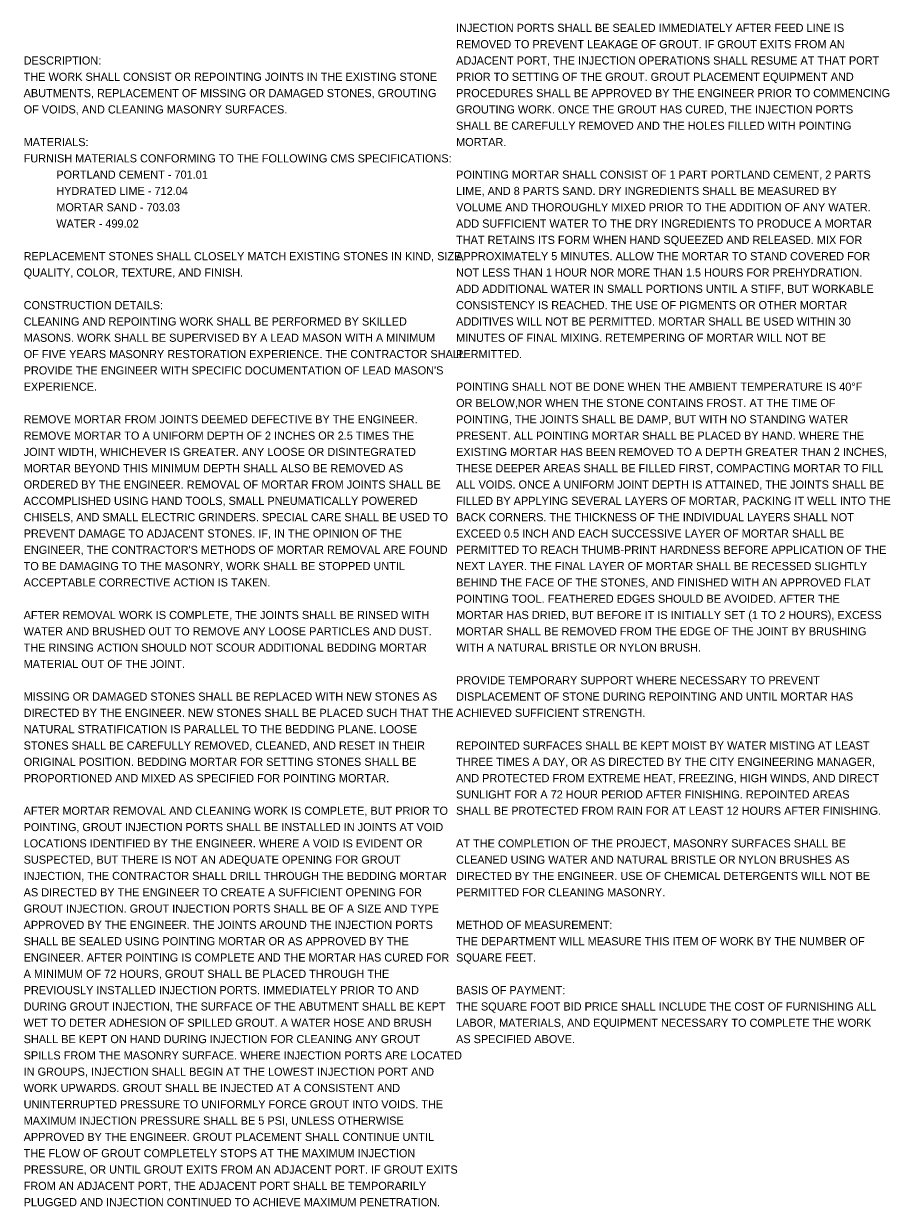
# Model space of a CAD drawing. Extents: x 0 to 59.1, y 0 to 43.6.
# Drawn here: x 9.82 to 24.69, y 23.33 to 43.63 of the extents above; entities that cross this region are included whole.
import ezdxf

# ---------------------------------------------------------------- set-up
doc = ezdxf.new("R2010")
doc.units = 0
doc.layers.add('SH_Text', color=7, linetype='Continuous')

msp = doc.modelspace()

# ---------------------------------------------------------------- texts
at = {"layer": 'SH_Text'}
for s, p in [('INJECTION PORTS SHALL BE SEALED IMMEDIATELY AFTER FEED LINE IS ', (17.24, 43.491)), ('REMOVED TO PREVENT LEAKAGE OF GROUT. IF GROUT EXITS FROM AN ', (17.24, 43.211)), ('DESCRIPTION:', (9.82, 42.931)), ('ADJACENT PORT, THE INJECTION OPERATIONS SHALL RESUME AT THAT PORT ', (17.24, 42.931)), ('THE WORK SHALL CONSIST OR REPOINTING JOINTS IN THE EXISTING STONE ', (9.82, 42.651)), ('PRIOR TO SETTING OF THE GROUT. GROUT PLACEMENT EQUIPMENT AND ', (17.24, 42.651)), ('ABUTMENTS, REPLACEMENT OF MISSING OR DAMAGED STONES, GROUTING ', (9.82, 42.371)), ('PROCEDURES SHALL BE APPROVED BY THE ENGINEER PRIOR TO COMMENCING ', (17.24, 42.371)), ('OF VOIDS, AND CLEANING MASONRY SURFACES.', (9.82, 42.091)), ('GROUTING WORK. ONCE THE GROUT HAS CURED, THE INJECTION PORTS ', (17.24, 42.091)), ('SHALL BE CAREFULLY REMOVED AND THE HOLES FILLED WITH POINTING ', (17.24, 41.811)), ('MATERIALS:', (9.82, 41.531)), ('MORTAR.', (17.24, 41.531)), ('FURNISH MATERIALS CONFORMING TO THE FOLLOWING CMS SPECIFICATIONS:', (9.82, 41.251)), ('PORTLAND CEMENT - 701.01', (10.38, 40.971)), ('POINTING MORTAR SHALL CONSIST OF 1 PART PORTLAND CEMENT, 2 PARTS ', (17.24, 40.971)), ('HYDRATED LIME - 712.04', (10.38, 40.691)), ('LIME, AND 8 PARTS SAND. DRY INGREDIENTS SHALL BE MEASURED BY ', (17.24, 40.691)), ('MORTAR SAND - 703.03', (10.38, 40.411)), ('VOLUME AND THOROUGHLY MIXED PRIOR TO THE ADDITION OF ANY WATER. ', (17.24, 40.411)), ('WATER - 499.02', (10.38, 40.131)), ('ADD SUFFICIENT WATER TO THE DRY INGREDIENTS TO PRODUCE A MORTAR ', (17.24, 40.131)), ('THAT RETAINS ITS FORM WHEN HAND SQUEEZED AND RELEASED. MIX FOR ', (17.24, 39.851)), ('REPLACEMENT STONES SHALL CLOSELY MATCH EXISTING STONES IN KIND, SIZE, ', (9.82, 39.571)), ('APPROXIMATELY 5 MINUTES. ALLOW THE MORTAR TO STAND COVERED FOR ', (17.24, 39.571)), ('QUALITY, COLOR, TEXTURE, AND FINISH.', (9.82, 39.291)), ('NOT LESS THAN 1 HOUR NOR MORE THAN 1.5 HOURS FOR PREHYDRATION. ', (17.24, 39.291)), ('ADD ADDITIONAL WATER IN SMALL PORTIONS UNTIL A STIFF, BUT WORKABLE ', (17.24, 39.011)), ('CONSTRUCTION DETAILS:', (9.82, 38.731)), ('CONSISTENCY IS REACHED. THE USE OF PIGMENTS OR OTHER MORTAR ', (17.24, 38.731)), ('CLEANING AND REPOINTING WORK SHALL BE PERFORMED BY SKILLED ', (9.82, 38.451)), ('ADDITIVES WILL NOT BE PERMITTED. MORTAR SHALL BE USED WITHIN 30 ', (17.24, 38.451)), ('MASONS. WORK SHALL BE SUPERVISED BY A LEAD MASON WITH A MINIMUM ', (9.82, 38.171)), ('MINUTES OF FINAL MIXING. RETEMPERING OF MORTAR WILL NOT BE ', (17.24, 38.171)), ('OF FIVE YEARS MASONRY RESTORATION EXPERIENCE. THE CONTRACTOR SHALL ', (9.82, 37.891)), ('PERMITTED.', (17.24, 37.891)), ("PROVIDE THE ENGINEER WITH SPECIFIC DOCUMENTATION OF LEAD MASON'S", (9.82, 37.611)), ('EXPERIENCE.', (9.82, 37.331)), ('POINTING SHALL NOT BE DONE WHEN THE AMBIENT TEMPERATURE IS 40°F ', (17.24, 37.331)), ('OR BELOW,NOR WHEN THE STONE CONTAINS FROST. AT THE TIME OF ', (17.24, 37.051)), ('REMOVE MORTAR FROM JOINTS DEEMED DEFECTIVE BY THE ENGINEER. ', (9.82, 36.771)), ('POINTING, THE JOINTS SHALL BE DAMP, BUT WITH NO STANDING WATER ', (17.24, 36.771)), ('REMOVE MORTAR TO A UNIFORM DEPTH OF 2 INCHES OR 2.5 TIMES THE ', (9.82, 36.491)), ('PRESENT. ALL POINTING MORTAR SHALL BE PLACED BY HAND. WHERE THE ', (17.24, 36.491)), ('JOINT WIDTH, WHICHEVER IS GREATER. ANY LOOSE OR DISINTEGRATED ', (9.82, 36.211)), ('EXISTING MORTAR HAS BEEN REMOVED TO A DEPTH GREATER THAN 2 INCHES, ', (17.24, 36.211)), ('MORTAR BEYOND THIS MINIMUM DEPTH SHALL ALSO BE REMOVED AS ', (9.82, 35.931)), ('THESE DEEPER AREAS SHALL BE FILLED FIRST, COMPACTING MORTAR TO FILL ', (17.24, 35.931)), ('ORDERED BY THE ENGINEER. REMOVAL OF MORTAR FROM JOINTS SHALL BE ', (9.82, 35.651)), ('ALL VOIDS. ONCE A UNIFORM JOINT DEPTH IS ATTAINED, THE JOINTS SHALL BE ', (17.24, 35.651)), ('ACCOMPLISHED USING HAND TOOLS, SMALL PNEUMATICALLY POWERED ', (9.82, 35.371)), ('FILLED BY APPLYING SEVERAL LAYERS OF MORTAR, PACKING IT WELL INTO THE ', (17.24, 35.371)), ('CHISELS, AND SMALL ELECTRIC GRINDERS. SPECIAL CARE SHALL BE USED TO ', (9.82, 35.091)), ('BACK CORNERS. THE THICKNESS OF THE INDIVIDUAL LAYERS SHALL NOT ', (17.24, 35.091)), ('PREVENT DAMAGE TO ADJACENT STONES. IF, IN THE OPINION OF THE ', (9.82, 34.811)), ('EXCEED 0.5 INCH AND EACH SUCCESSIVE LAYER OF MORTAR SHALL BE ', (17.24, 34.811)), ("ENGINEER, THE CONTRACTOR'S METHODS OF MORTAR REMOVAL ARE FOUND ", (9.82, 34.531)), ('PERMITTED TO REACH THUMB-PRINT HARDNESS BEFORE APPLICATION OF THE ', (17.24, 34.531)), ('TO BE DAMAGING TO THE MASONRY, WORK SHALL BE STOPPED UNTIL ', (9.82, 34.251)), ('NEXT LAYER. THE FINAL LAYER OF MORTAR SHALL BE RECESSED SLIGHTLY ', (17.24, 34.251)), ('ACCEPTABLE CORRECTIVE ACTION IS TAKEN.', (9.82, 33.971)), ('BEHIND THE FACE OF THE STONES, AND FINISHED WITH AN APPROVED FLAT ', (17.24, 33.971)), ('POINTING TOOL. FEATHERED EDGES SHOULD BE AVOIDED. AFTER THE ', (17.24, 33.691)), ('AFTER REMOVAL WORK IS COMPLETE, THE JOINTS SHALL BE RINSED WITH ', (9.82, 33.411)), ('MORTAR HAS DRIED, BUT BEFORE IT IS INITIALLY SET (1 TO 2 HOURS), EXCESS ', (17.24, 33.411)), ('WATER AND BRUSHED OUT TO REMOVE ANY LOOSE PARTICLES AND DUST. ', (9.82, 33.131)), ('MORTAR SHALL BE REMOVED FROM THE EDGE OF THE JOINT BY BRUSHING ', (17.24, 33.131)), ('THE RINSING ACTION SHOULD NOT SCOUR ADDITIONAL BEDDING MORTAR ', (9.82, 32.851)), ('WITH A NATURAL BRISTLE OR NYLON BRUSH.', (17.24, 32.851)), ('MATERIAL OUT OF THE JOINT.', (9.82, 32.571)), ('PROVIDE TEMPORARY SUPPORT WHERE NECESSARY TO PREVENT ', (17.24, 32.291)), ('MISSING OR DAMAGED STONES SHALL BE REPLACED WITH NEW STONES AS ', (9.82, 32.011)), ('DISPLACEMENT OF STONE DURING REPOINTING AND UNTIL MORTAR HAS ', (17.24, 32.011)), ('DIRECTED BY THE ENGINEER. NEW STONES SHALL BE PLACED SUCH THAT THE ', (9.82, 31.731)), ('ACHIEVED SUFFICIENT STRENGTH.', (17.24, 31.731)), ('NATURAL STRATIFICATION IS PARALLEL TO THE BEDDING PLANE. LOOSE ', (9.82, 31.451)), ('STONES SHALL BE CAREFULLY REMOVED, CLEANED, AND RESET IN THEIR ', (9.82, 31.171)), ('REPOINTED SURFACES SHALL BE KEPT MOIST BY WATER MISTING AT LEAST ', (17.24, 31.171)), ('ORIGINAL POSITION. BEDDING MORTAR FOR SETTING STONES SHALL BE ', (9.82, 30.891)), ('THREE TIMES A DAY, OR AS DIRECTED BY THE CITY ENGINEERING MANAGER, ', (17.24, 30.891)), ('PROPORTIONED AND MIXED AS SPECIFIED FOR POINTING MORTAR.', (9.82, 30.611)), ('AND PROTECTED FROM EXTREME HEAT, FREEZING, HIGH WINDS, AND DIRECT ', (17.24, 30.611)), ('SUNLIGHT FOR A 72 HOUR PERIOD AFTER FINISHING. REPOINTED AREAS ', (17.24, 30.331)), ('AFTER MORTAR REMOVAL AND CLEANING WORK IS COMPLETE, BUT PRIOR TO ', (9.82, 30.051)), ('SHALL BE PROTECTED FROM RAIN FOR AT LEAST 12 HOURS AFTER FINISHING.', (17.24, 30.051)), ('POINTING, GROUT INJECTION PORTS SHALL BE INSTALLED IN JOINTS AT VOID ', (9.82, 29.771)), ('LOCATIONS IDENTIFIED BY THE ENGINEER. WHERE A VOID IS EVIDENT OR ', (9.82, 29.491)), ('AT THE COMPLETION OF THE PROJECT, MASONRY SURFACES SHALL BE ', (17.24, 29.491)), ('SUSPECTED, BUT THERE IS NOT AN ADEQUATE OPENING FOR GROUT ', (9.82, 29.211)), ('CLEANED USING WATER AND NATURAL BRISTLE OR NYLON BRUSHES AS ', (17.24, 29.211)), ('INJECTION, THE CONTRACTOR SHALL DRILL THROUGH THE BEDDING MORTAR ', (9.82, 28.931)), ('DIRECTED BY THE ENGINEER. USE OF CHEMICAL DETERGENTS WILL NOT BE ', (17.24, 28.931)), ('AS DIRECTED BY THE ENGINEER TO CREATE A SUFFICIENT OPENING FOR ', (9.82, 28.651)), ('PERMITTED FOR CLEANING MASONRY.', (17.24, 28.651)), ('GROUT INJECTION. GROUT INJECTION PORTS SHALL BE OF A SIZE AND TYPE ', (9.82, 28.371)), ('APPROVED BY THE ENGINEER. THE JOINTS AROUND THE INJECTION PORTS ', (9.82, 28.091)), ('METHOD OF MEASUREMENT:', (17.24, 28.091)), ('SHALL BE SEALED USING POINTING MORTAR OR AS APPROVED BY THE ', (9.82, 27.811)), ('THE DEPARTMENT WILL MEASURE THIS ITEM OF WORK BY THE NUMBER OF ', (17.24, 27.811)), ('ENGINEER. AFTER POINTING IS COMPLETE AND THE MORTAR HAS CURED FOR ', (9.82, 27.531)), ('SQUARE FEET.', (17.24, 27.531)), ('A MINIMUM OF 72 HOURS, GROUT SHALL BE PLACED THROUGH THE ', (9.82, 27.251)), ('PREVIOUSLY INSTALLED INJECTION PORTS. IMMEDIATELY PRIOR TO AND ', (9.82, 26.971)), ('BASIS OF PAYMENT:', (17.24, 26.971)), ('DURING GROUT INJECTION, THE SURFACE OF THE ABUTMENT SHALL BE KEPT ', (9.82, 26.691)), ('THE SQUARE FOOT BID PRICE SHALL INCLUDE THE COST OF FURNISHING ALL ', (17.24, 26.691)), ('WET TO DETER ADHESION OF SPILLED GROUT. A WATER HOSE AND BRUSH ', (9.82, 26.411)), ('LABOR, MATERIALS, AND EQUIPMENT NECESSARY TO COMPLETE THE WORK ', (17.24, 26.411)), ('SHALL BE KEPT ON HAND DURING INJECTION FOR CLEANING ANY GROUT ', (9.82, 26.131)), ('AS SPECIFIED ABOVE.', (17.24, 26.131)), ('SPILLS FROM THE MASONRY SURFACE. WHERE INJECTION PORTS ARE LOCATED ', (9.82, 25.851)), ('IN GROUPS, INJECTION SHALL BEGIN AT THE LOWEST INJECTION PORT AND ', (9.82, 25.571)), ('WORK UPWARDS. GROUT SHALL BE INJECTED AT A CONSISTENT AND ', (9.82, 25.291)), ('UNINTERRUPTED PRESSURE TO UNIFORMLY FORCE GROUT INTO VOIDS. THE ', (9.82, 25.011)), ('MAXIMUM INJECTION PRESSURE SHALL BE 5 PSI, UNLESS OTHERWISE ', (9.82, 24.731)), ('APPROVED BY THE ENGINEER. GROUT PLACEMENT SHALL CONTINUE UNTIL ', (9.82, 24.451)), ('THE FLOW OF GROUT COMPLETELY STOPS AT THE MAXIMUM INJECTION ', (9.82, 24.171)), ('PRESSURE, OR UNTIL GROUT EXITS FROM AN ADJACENT PORT. IF GROUT EXITS ', (9.82, 23.891)), ('FROM AN ADJACENT PORT, THE ADJACENT PORT SHALL BE TEMPORARILY ', (9.82, 23.611)), ('PLUGGED AND INJECTION CONTINUED TO ACHIEVE MAXIMUM PENETRATION. ', (9.82, 23.331))]:
    msp.add_text(s, height=0.14, dxfattribs=at).set_placement(p)

doc.saveas('drawing.dxf')
